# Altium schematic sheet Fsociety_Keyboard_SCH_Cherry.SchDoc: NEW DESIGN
size A2; CompanyName: Rena Electronica; Engineer: IK; Organization: Rena Electronica; Address1: de Ambachten 12; Address2: 4881 XZ; Address3: Zundert; Address4: the Netherlands; DocumentNumber: 05.xxx; Revision: 0.10; Customer: Klantnaam; PageSetup: Record=PageOptions¦CenterHorizontal=True¦CenterVertical=True¦PrintScale=0.73¦XCorrection=1.00¦YCorrection=1.00¦PrintKind=0¦BorderSize=5000000¦LeftOffset=0¦BottomOffset=0¦Orientation=2¦PaperLength=1000¦PaperWidth=1000¦Scale=100¦PaperSource=7¦PrintQuality=-3¦MediaType=1¦DitherType=10¦PrintScaleMode=1¦PaperKind=A3¦PaperIndex=8
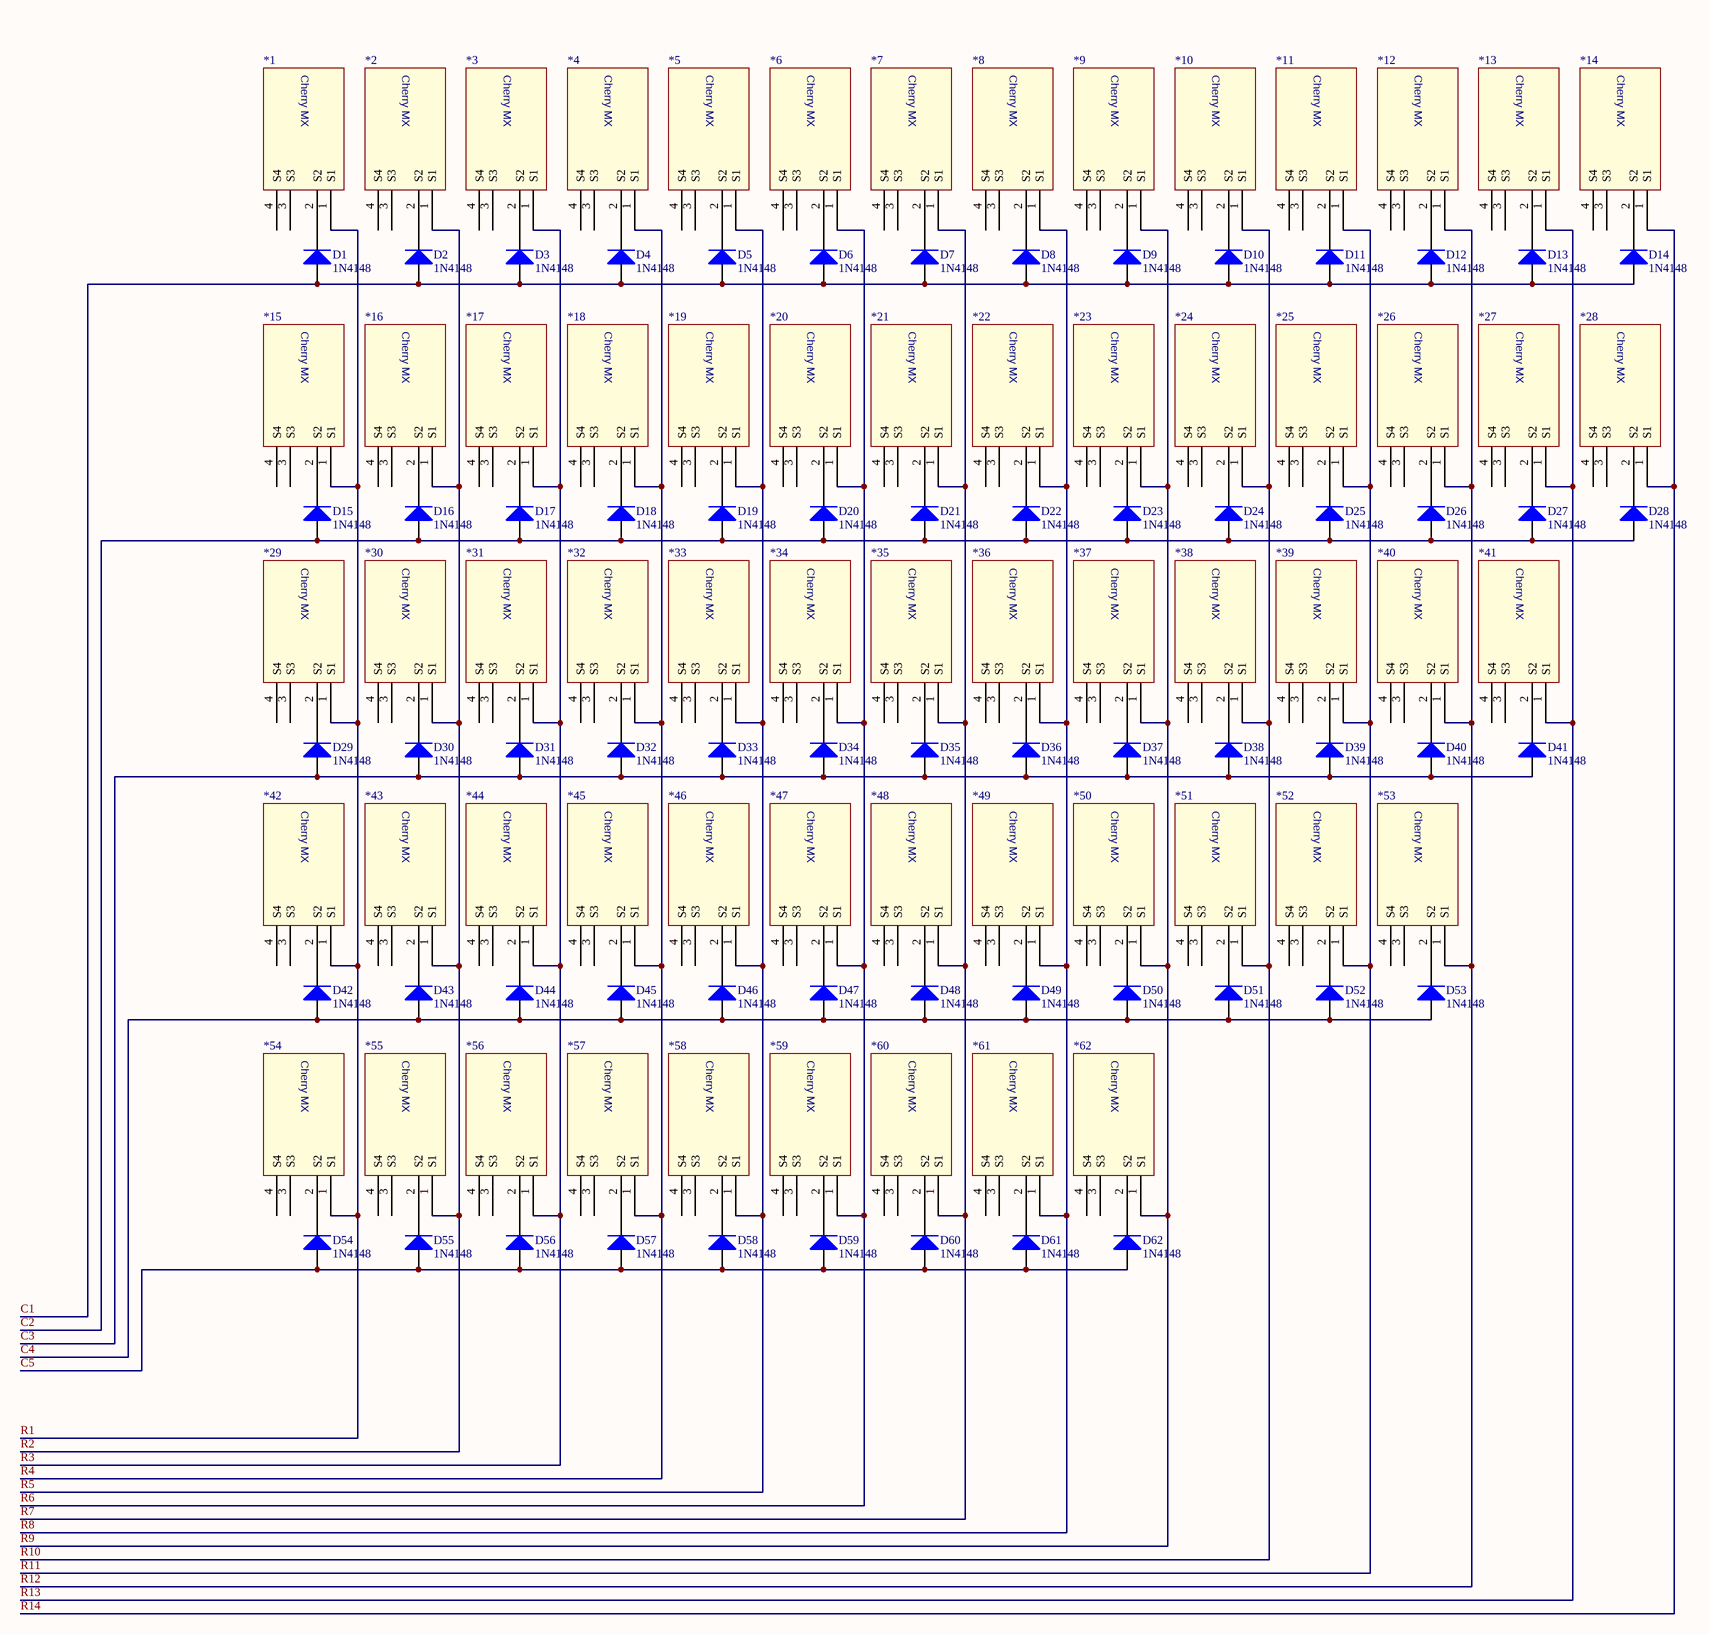
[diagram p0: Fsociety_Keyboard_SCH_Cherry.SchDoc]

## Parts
*1  CHERRY_MX  [CherryMX]  (value not drawn)
*2  CHERRY_MX  [CherryMX]  (value not drawn)
*3  CHERRY_MX  [CherryMX]  (value not drawn)
*4  CHERRY_MX  [CherryMX]  (value not drawn)
*5  CHERRY_MX  [CherryMX]  (value not drawn)
*6  CHERRY_MX  [CherryMX]  (value not drawn)
*7  CHERRY_MX  [CherryMX]  (value not drawn)
*8  CHERRY_MX  [CherryMX]  (value not drawn)
*9  CHERRY_MX  [CherryMX]  (value not drawn)
*10  CHERRY_MX  [CherryMX]  (value not drawn)
*11  CHERRY_MX  [CherryMX]  (value not drawn)
*12  CHERRY_MX  [CherryMX]  (value not drawn)
*13  CHERRY_MX  [CherryMX]  (value not drawn)
*14  CHERRY_MX  [CherryMX]  (value not drawn)
*15  CHERRY_MX  [CherryMX]  (value not drawn)
*16  CHERRY_MX  [CherryMX]  (value not drawn)
*17  CHERRY_MX  [CherryMX]  (value not drawn)
*18  CHERRY_MX  [CherryMX]  (value not drawn)
*19  CHERRY_MX  [CherryMX]  (value not drawn)
*20  CHERRY_MX  [CherryMX]  (value not drawn)
*21  CHERRY_MX  [CherryMX]  (value not drawn)
*22  CHERRY_MX  [CherryMX]  (value not drawn)
*23  CHERRY_MX  [CherryMX]  (value not drawn)
*24  CHERRY_MX  [CherryMX]  (value not drawn)
*25  CHERRY_MX  [CherryMX]  (value not drawn)
*26  CHERRY_MX  [CherryMX]  (value not drawn)
*27  CHERRY_MX  [CherryMX]  (value not drawn)
*28  CHERRY_MX  [CherryMX]  (value not drawn)
*29  CHERRY_MX  [CherryMX]  (value not drawn)
*30  CHERRY_MX  [CherryMX]  (value not drawn)
*31  CHERRY_MX  [CherryMX]  (value not drawn)
*32  CHERRY_MX  [CherryMX]  (value not drawn)
*33  CHERRY_MX  [CherryMX]  (value not drawn)
*34  CHERRY_MX  [CherryMX]  (value not drawn)
*35  CHERRY_MX  [CherryMX]  (value not drawn)
*36  CHERRY_MX  [CherryMX]  (value not drawn)
*37  CHERRY_MX  [CherryMX]  (value not drawn)
*38  CHERRY_MX  [CherryMX]  (value not drawn)
*39  CHERRY_MX  [CherryMX]  (value not drawn)
*40  CHERRY_MX  [CherryMX]  (value not drawn)
*41  CHERRY_MX  [CherryMX]  (value not drawn)
*42  CHERRY_MX  [CherryMX]  (value not drawn)
*43  CHERRY_MX  [CherryMX]  (value not drawn)
*44  CHERRY_MX  [CherryMX]  (value not drawn)
*45  CHERRY_MX  [CherryMX]  (value not drawn)
*46  CHERRY_MX  [CherryMX]  (value not drawn)
*47  CHERRY_MX  [CherryMX]  (value not drawn)
*48  CHERRY_MX  [CherryMX]  (value not drawn)
*49  CHERRY_MX  [CherryMX]  (value not drawn)
*50  CHERRY_MX  [CherryMX]  (value not drawn)
*51  CHERRY_MX  [CherryMX]  (value not drawn)
*52  CHERRY_MX  [CherryMX]  (value not drawn)
*53  CHERRY_MX  [CherryMX]  (value not drawn)
*54  CHERRY_MX  [CherryMX]  (value not drawn)
*55  CHERRY_MX  [CherryMX]  (value not drawn)
*56  CHERRY_MX  [CherryMX]  (value not drawn)
*57  CHERRY_MX  [CherryMX]  (value not drawn)
*58  CHERRY_MX  [CherryMX]  (value not drawn)
*59  CHERRY_MX  [CherryMX]  (value not drawn)
*60  CHERRY_MX  [CherryMX]  (value not drawn)
*61  CHERRY_MX  [CherryMX]  (value not drawn)
*62  CHERRY_MX  [CherryMX]  (value not drawn)
D1  1N4148  [DIOMELF3515_NR_SOD80C]
D2  1N4148  [DIOMELF3515_NR_SOD80C]
D3  1N4148  [DIOMELF3515_NR_SOD80C]
D4  1N4148  [DIOMELF3515_NR_SOD80C]
D5  1N4148  [DIOMELF3515_NR_SOD80C]
D6  1N4148  [DIOMELF3515_NR_SOD80C]
D7  1N4148  [DIOMELF3515_NR_SOD80C]
D8  1N4148  [DIOMELF3515_NR_SOD80C]
D9  1N4148  [DIOMELF3515_NR_SOD80C]
D10  1N4148  [DIOMELF3515_NR_SOD80C]
D11  1N4148  [DIOMELF3515_NR_SOD80C]
D12  1N4148  [DIOMELF3515_NR_SOD80C]
D13  1N4148  [DIOMELF3515_NR_SOD80C]
D14  1N4148  [DIOMELF3515_NR_SOD80C]
D15  1N4148  [DIOMELF3515_NR_SOD80C]
D16  1N4148  [DIOMELF3515_NR_SOD80C]
D17  1N4148  [DIOMELF3515_NR_SOD80C]
D18  1N4148  [DIOMELF3515_NR_SOD80C]
D19  1N4148  [DIOMELF3515_NR_SOD80C]
D20  1N4148  [DIOMELF3515_NR_SOD80C]
D21  1N4148  [DIOMELF3515_NR_SOD80C]
D22  1N4148  [DIOMELF3515_NR_SOD80C]
D23  1N4148  [DIOMELF3515_NR_SOD80C]
D24  1N4148  [DIOMELF3515_NR_SOD80C]
D25  1N4148  [DIOMELF3515_NR_SOD80C]
D26  1N4148  [DIOMELF3515_NR_SOD80C]
D27  1N4148  [DIOMELF3515_NR_SOD80C]
D28  1N4148  [DIOMELF3515_NR_SOD80C]
D29  1N4148  [DIOMELF3515_NR_SOD80C]
D30  1N4148  [DIOMELF3515_NR_SOD80C]
D31  1N4148  [DIOMELF3515_NR_SOD80C]
D32  1N4148  [DIOMELF3515_NR_SOD80C]
D33  1N4148  [DIOMELF3515_NR_SOD80C]
D34  1N4148  [DIOMELF3515_NR_SOD80C]
D35  1N4148  [DIOMELF3515_NR_SOD80C]
D36  1N4148  [DIOMELF3515_NR_SOD80C]
D37  1N4148  [DIOMELF3515_NR_SOD80C]
D38  1N4148  [DIOMELF3515_NR_SOD80C]
D39  1N4148  [DIOMELF3515_NR_SOD80C]
D40  1N4148  [DIOMELF3515_NR_SOD80C]
D41  1N4148  [DIOMELF3515_NR_SOD80C]
D42  1N4148  [DIOMELF3515_NR_SOD80C]
D43  1N4148  [DIOMELF3515_NR_SOD80C]
D44  1N4148  [DIOMELF3515_NR_SOD80C]
D45  1N4148  [DIOMELF3515_NR_SOD80C]
D46  1N4148  [DIOMELF3515_NR_SOD80C]
D47  1N4148  [DIOMELF3515_NR_SOD80C]
D48  1N4148  [DIOMELF3515_NR_SOD80C]
D49  1N4148  [DIOMELF3515_NR_SOD80C]
D50  1N4148  [DIOMELF3515_NR_SOD80C]
D51  1N4148  [DIOMELF3515_NR_SOD80C]
D52  1N4148  [DIOMELF3515_NR_SOD80C]
D53  1N4148  [DIOMELF3515_NR_SOD80C]
D54  1N4148  [DIOMELF3515_NR_SOD80C]
D55  1N4148  [DIOMELF3515_NR_SOD80C]
D56  1N4148  [DIOMELF3515_NR_SOD80C]
D57  1N4148  [DIOMELF3515_NR_SOD80C]
D58  1N4148  [DIOMELF3515_NR_SOD80C]
D59  1N4148  [DIOMELF3515_NR_SOD80C]
D60  1N4148  [DIOMELF3515_NR_SOD80C]
D61  1N4148  [DIOMELF3515_NR_SOD80C]
D62  1N4148  [DIOMELF3515_NR_SOD80C]

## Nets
C1: D1.A D2.A D3.A D4.A D5.A D6.A D7.A D8.A D9.A D10.A D11.A D12.A D13.A D14.A
C2: D15.A D16.A D17.A D18.A D19.A D20.A D21.A D22.A D23.A D24.A D25.A D26.A D27.A D28.A
C3: D29.A D30.A D31.A D32.A D33.A D34.A D35.A D36.A D37.A D38.A D39.A D40.A D41.A
C4: D42.A D43.A D44.A D45.A D46.A D47.A D48.A D49.A D50.A D51.A D52.A D53.A
C5: D54.A D55.A D56.A D57.A D58.A D59.A D60.A D61.A D62.A
R1: *1.1(S1) *15.1(S1) *29.1(S1) *42.1(S1) *54.1(S1)
R2: *2.1(S1) *16.1(S1) *30.1(S1) *43.1(S1) *55.1(S1)
R3: *3.1(S1) *17.1(S1) *31.1(S1) *44.1(S1) *56.1(S1)
R4: *4.1(S1) *18.1(S1) *32.1(S1) *45.1(S1) *57.1(S1)
R5: *5.1(S1) *19.1(S1) *33.1(S1) *46.1(S1) *58.1(S1)
R6: *6.1(S1) *20.1(S1) *34.1(S1) *47.1(S1) *59.1(S1)
R7: *7.1(S1) *21.1(S1) *35.1(S1) *48.1(S1) *60.1(S1)
R8: *8.1(S1) *22.1(S1) *36.1(S1) *49.1(S1) *61.1(S1)
R9: *9.1(S1) *23.1(S1) *37.1(S1) *50.1(S1) *62.1(S1)
R10: *10.1(S1) *24.1(S1) *38.1(S1) *51.1(S1)
R11: *11.1(S1) *25.1(S1) *39.1(S1) *52.1(S1)
R12: *12.1(S1) *26.1(S1) *40.1(S1) *53.1(S1)
R13: *13.1(S1) *27.1(S1) *41.1(S1)
R14: *14.1(S1) *28.1(S1)
Net*1_2: *1.2(S2) D1.C
Net*2_2: *2.2(S2) D2.C
Net*3_2: *3.2(S2) D3.C
Net*4_2: *4.2(S2) D4.C
Net*5_2: *5.2(S2) D5.C
Net*6_2: *6.2(S2) D6.C
Net*7_2: *7.2(S2) D7.C
Net*8_2: *8.2(S2) D8.C
Net*9_2: *9.2(S2) D9.C
Net*10_2: *10.2(S2) D10.C
Net*11_2: *11.2(S2) D11.C
Net*12_2: *12.2(S2) D12.C
Net*13_2: *13.2(S2) D13.C
Net*14_2: *14.2(S2) D14.C
Net*15_2: *15.2(S2) D15.C
Net*16_2: *16.2(S2) D16.C
Net*17_2: *17.2(S2) D17.C
Net*18_2: *18.2(S2) D18.C
Net*19_2: *19.2(S2) D19.C
Net*20_2: *20.2(S2) D20.C
Net*21_2: *21.2(S2) D21.C
Net*22_2: *22.2(S2) D22.C
Net*23_2: *23.2(S2) D23.C
Net*24_2: *24.2(S2) D24.C
Net*25_2: *25.2(S2) D25.C
Net*26_2: *26.2(S2) D26.C
Net*27_2: *27.2(S2) D27.C
Net*28_2: *28.2(S2) D28.C
Net*29_2: *29.2(S2) D29.C
Net*30_2: *30.2(S2) D30.C
Net*31_2: *31.2(S2) D31.C
Net*32_2: *32.2(S2) D32.C
Net*33_2: *33.2(S2) D33.C
Net*34_2: *34.2(S2) D34.C
Net*35_2: *35.2(S2) D35.C
Net*36_2: *36.2(S2) D36.C
Net*37_2: *37.2(S2) D37.C
Net*38_2: *38.2(S2) D38.C
Net*39_2: *39.2(S2) D39.C
Net*40_2: *40.2(S2) D40.C
Net*41_2: *41.2(S2) D41.C
Net*42_2: *42.2(S2) D42.C
Net*43_2: *43.2(S2) D43.C
Net*44_2: *44.2(S2) D44.C
Net*45_2: *45.2(S2) D45.C
Net*46_2: *46.2(S2) D46.C
Net*47_2: *47.2(S2) D47.C
Net*48_2: *48.2(S2) D48.C
Net*49_2: *49.2(S2) D49.C
Net*50_2: *50.2(S2) D50.C
Net*51_2: *51.2(S2) D51.C
Net*52_2: *52.2(S2) D52.C
Net*53_2: *53.2(S2) D53.C
Net*54_2: *54.2(S2) D54.C
Net*55_2: *55.2(S2) D55.C
Net*56_2: *56.2(S2) D56.C
Net*57_2: *57.2(S2) D57.C
Net*58_2: *58.2(S2) D58.C
Net*59_2: *59.2(S2) D59.C
Net*60_2: *60.2(S2) D60.C
Net*61_2: *61.2(S2) D61.C
Net*62_2: *62.2(S2) D62.C

Not connected (* = marked no-connect by the designer): *1 3(S3) 4(S4); *2 3(S3) 4(S4); *3 3(S3) 4(S4); *4 3(S3) 4(S4); *5 3(S3) 4(S4); *6 3(S3) 4(S4); *7 3(S3) 4(S4); *8 3(S3) 4(S4); *9 3(S3) 4(S4); *10 3(S3) 4(S4); *11 3(S3) 4(S4); *12 3(S3) 4(S4); *13 3(S3) 4(S4); *14 3(S3) 4(S4); *15 3(S3) 4(S4); *16 3(S3) 4(S4); *17 3(S3) 4(S4); *18 3(S3) 4(S4); *19 3(S3) 4(S4); *20 3(S3) 4(S4); *21 3(S3) 4(S4); *22 3(S3) 4(S4); *23 3(S3) 4(S4); *24 3(S3) 4(S4); *25 3(S3) 4(S4); *26 3(S3) 4(S4); *27 3(S3) 4(S4); *28 3(S3) 4(S4); *29 3(S3) 4(S4); *30 3(S3) 4(S4); *31 3(S3) 4(S4); *32 3(S3) 4(S4); *33 3(S3) 4(S4); *34 3(S3) 4(S4); *35 3(S3) 4(S4); *36 3(S3) 4(S4); *37 3(S3) 4(S4); *38 3(S3) 4(S4); *39 3(S3) 4(S4); *40 3(S3) 4(S4); *41 3(S3) 4(S4); *42 3(S3) 4(S4); *43 3(S3) 4(S4); *44 3(S3) 4(S4); *45 3(S3) 4(S4); *46 3(S3) 4(S4); *47 3(S3) 4(S4); *48 3(S3) 4(S4); *49 3(S3) 4(S4); *50 3(S3) 4(S4); *51 3(S3) 4(S4); *52 3(S3) 4(S4); *53 3(S3) 4(S4); *54 3(S3) 4(S4); *55 3(S3) 4(S4); *56 3(S3) 4(S4); *57 3(S3) 4(S4); *58 3(S3) 4(S4); *59 3(S3) 4(S4); *60 3(S3) 4(S4); *61 3(S3) 4(S4); *62 3(S3) 4(S4)

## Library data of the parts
D1-D62 = CMP-00137-A.4: Diode 1N4148 SOD80(SMT); MAXPartNumber: 1N4148!; PartNumber: LL4148-GS18-LF; Manufacturer: Vishay; IFSM Max (A): 0.5; Packing: Tape en Reel; Type: Fast; Reverse Voltage: 100V; Forward Voltage: ? V; IF (Cont): ? A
